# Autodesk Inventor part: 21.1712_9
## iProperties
Created: 2007-05
Part Number: 21.1712_9
Document SubType Name: Modeling
Designer: Andy Moles
Material: Steel
Mass: 27.5518 g
Surface Area: 29.6334 cm^2
Volume: 3.50978 cm^3
Density: 7.85 g/cm^3
Description: DOOR CHAIN CLAMP BODY LOW PROF.
Author: Andy Moles
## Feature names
1. Base1
2. Extrusion1
